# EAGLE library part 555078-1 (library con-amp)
AMP connector
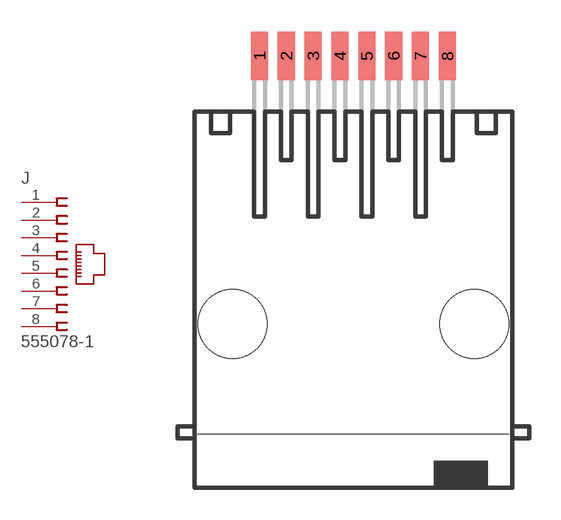
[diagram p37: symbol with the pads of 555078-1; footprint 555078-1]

Designator prefix J

## 555078-1 (MPN: 5555078-1; OC_FARNELL: 1771058; OC_NEWARK: 19R2773)  [555078-1]
1  1  pas
2  2  pas
3  3  pas
4  4  pas
5  5  pas
6  6  pas
7  7  pas
8  8  pas

## Footprint 555078-1 (pad centres in mm)
Modular Jack Keyed with Panel Stops
smd 0.813 x 2.286: 1 -4.445,11.533; 2 -3.175,11.533; 3 -1.905,11.533; 4 -0.635,11.533; 5 0.635,11.533; 6 1.905,11.533; 7 3.175,11.533; 8 4.445,11.533
hole 3.251 at -5.715,-1.143
hole 3.251 at 5.715,-1.143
